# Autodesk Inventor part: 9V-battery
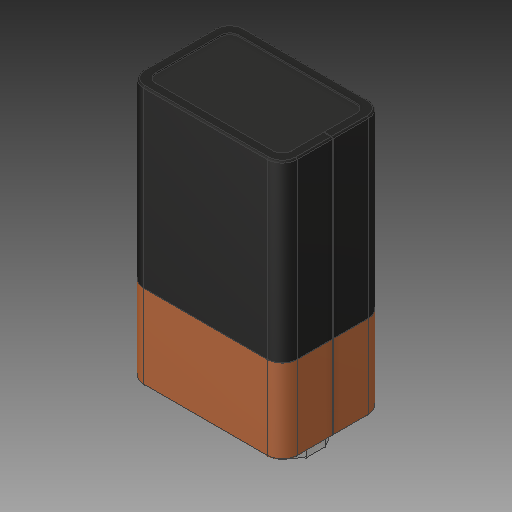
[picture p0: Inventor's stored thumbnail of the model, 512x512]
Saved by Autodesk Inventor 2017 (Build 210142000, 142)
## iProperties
Created: 2011-06
Part Number: 9V-battery
Material: Générique
Document SubType Name: Modeling
Designer: ficho
Mass: 19.2857 g
Surface Area: 48.6741 cm^2
Volume: 19.2857 cm^3
Density: 1 g/cm^3
Appearance: Par défaut
Title: icpv2
Author: keycreator
Revision Number: NONE
Sending System: Kubotek KeyCreator 2011 V10.0.0 (21019)
Preprocessor: Spatial Interop R20 SP3
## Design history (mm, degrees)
feature "layer1[1]"
node "Solide1"
